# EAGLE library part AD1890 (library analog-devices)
SamplePort Stereo Asynchronous Sample Rate Converters Auto generated by make-symbol-device-package-bsdl.ulp Rev. 33 Source: http://www.analog.com/static/imported-files/data_sheets/AD1890_1891.pdf
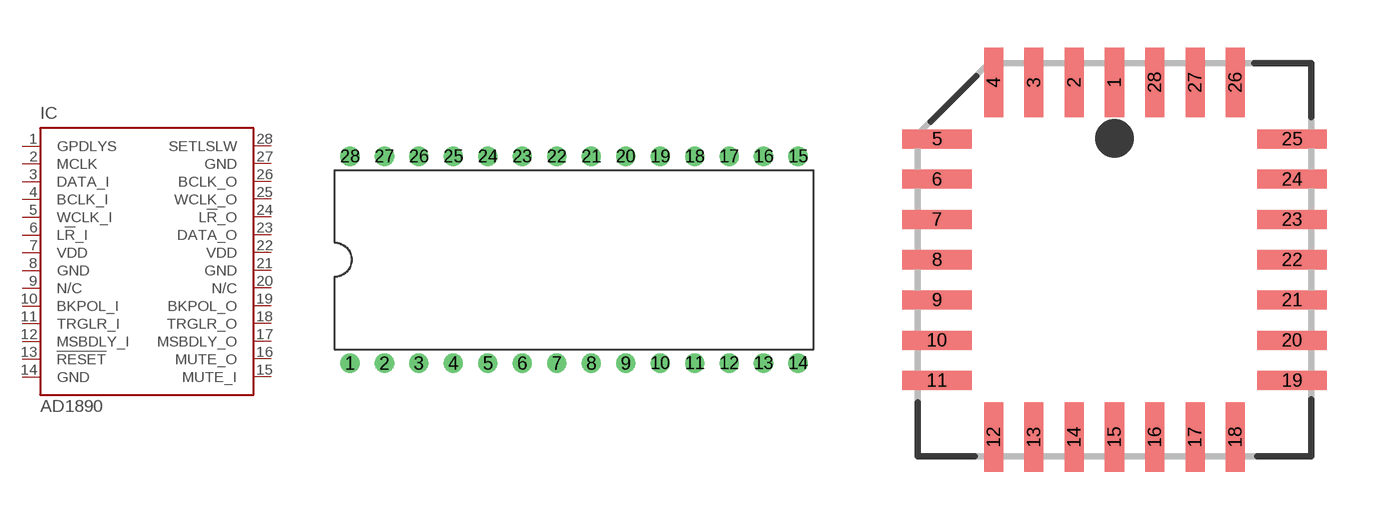
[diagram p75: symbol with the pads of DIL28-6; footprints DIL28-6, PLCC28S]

Designator prefix IC

## AD1890JN (OC_FARNELL: unknown; OC_NEWARK: unknown)  [DIL28-6]
1  GPDLYS  in
2  MCLK  in
3  DATA_I  in
4  BCLK_I  in
5  WCLK_I  in
6  L!R!_I  in
7  VDD  pwr
8  GND  pwr
9  N/C  nc
10  BKPOL_I  in
11  TRGLR_I  in
12  MSBDLY_I  in
13  !RESET  in
14  GND  pwr
15  MUTE_I  in
16  MUTE_O  out
17  MSBDLY_O  in
18  TRGLR_O  in
19  BKPOL_O  in
20  N/C  nc
21  GND  pwr
22  VDD  pwr
23  DATA_O  out
24  L!R!_O  in
25  WCLK_O  in
26  BCLK_O  in
27  GND  pwr
28  SETLSLW  in

## AD1890JP (MF: ALTERA CORPORATION; MPN: AD1890JP; OC_FARNELL: 1464273; OC_NEWARK: 66F1855)  [PLCC28S]
Pads as for DIL28-6

## Footprint DIL28-6 (pad centres in mm)
Dual In Line Package 0.6 inch
drill 0.813 pad 1.422 round: 1 -16.51,-7.62; 2 -13.97,-7.62; 3 -11.43,-7.62; 4 -8.89,-7.62; 5 -6.35,-7.62; 6 -3.81,-7.62; 7 -1.27,-7.62; 8 1.27,-7.62; 9 3.81,-7.62; 10 6.35,-7.62; 11 8.89,-7.62; 12 11.43,-7.62; 13 13.97,-7.62; 14 16.51,-7.62; 15 16.51,7.62; 16 13.97,7.62; 17 11.43,7.62; 18 8.89,7.62; 19 6.35,7.62; 20 3.81,7.62; 21 1.27,7.62; 22 -1.27,7.62; 23 -3.81,7.62; 24 -6.35,7.62; 25 -8.89,7.62; 26 -11.43,7.62; 27 -13.97,7.62; 28 -16.51,7.62

## Footprint PLCC28S (pad centres in mm)
PLASTIC LEADED CHIP CARRIER
smd 0.6 x 2.2: 1 0,5.6; 2 -1.27,5.6; 3 -2.54,5.6; 4 -3.81,5.6; 12 -3.81,-5.6; 13 -2.54,-5.6; 14 -1.27,-5.6; 15 0,-5.6; 16 1.27,-5.6; 17 2.54,-5.6; 18 3.81,-5.6; 26 3.81,5.6; 27 2.54,5.6; 28 1.27,5.6
smd 2.2 x 0.6: 5 -5.6,3.81; 6 -5.6,2.54; 7 -5.6,1.27; 8 -5.6,0; 9 -5.6,-1.27; 10 -5.6,-2.54; 11 -5.6,-3.81; 19 5.6,-3.81; 20 5.6,-2.54; 21 5.6,-1.27; 22 5.6,0; 23 5.6,1.27; 24 5.6,2.54; 25 5.6,3.81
